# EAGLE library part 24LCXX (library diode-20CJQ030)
Serial I2C bus eeprom
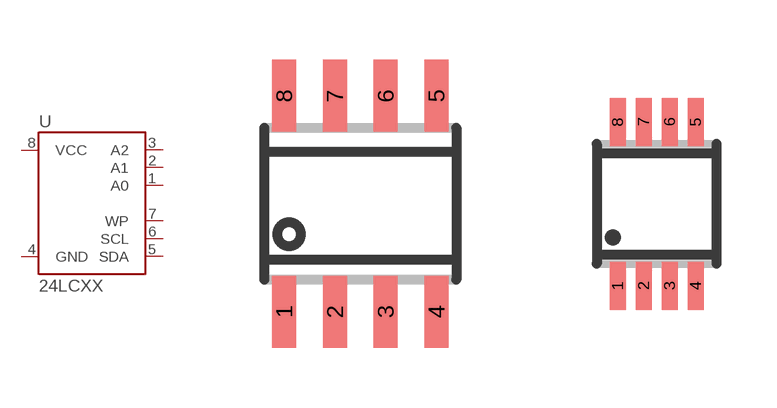
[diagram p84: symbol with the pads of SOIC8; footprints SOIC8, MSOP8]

Designator prefix U

## 24LCXX  [SOIC8]
1  A0  in
2  A1  in
3  A2  in
4  GND  pwr
5  SDA
6  SCL
7  WP  in
8  VCC  pwr

## 24LCXXM  [MSOP8]
Pads as for SOIC8

## Footprint SOIC8 (pad centres in mm)
Small Outline IC
smd 0.6 x 1.8: 1 -1.905,-2.7; 2 -0.635,-2.7; 3 0.635,-2.7; 4 1.905,-2.7; 5 1.905,2.7; 6 0.635,2.7; 7 -0.635,2.7; 8 -1.905,2.7

## Footprint MSOP8 (pad centres in mm)
MSOP8
smd 0.4 x 1.2: 1 -0.975,-2.05; 2 -0.325,-2.05; 3 0.325,-2.05; 4 0.975,-2.05; 5 0.975,2.05; 6 0.325,2.05; 7 -0.325,2.05; 8 -0.975,2.05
